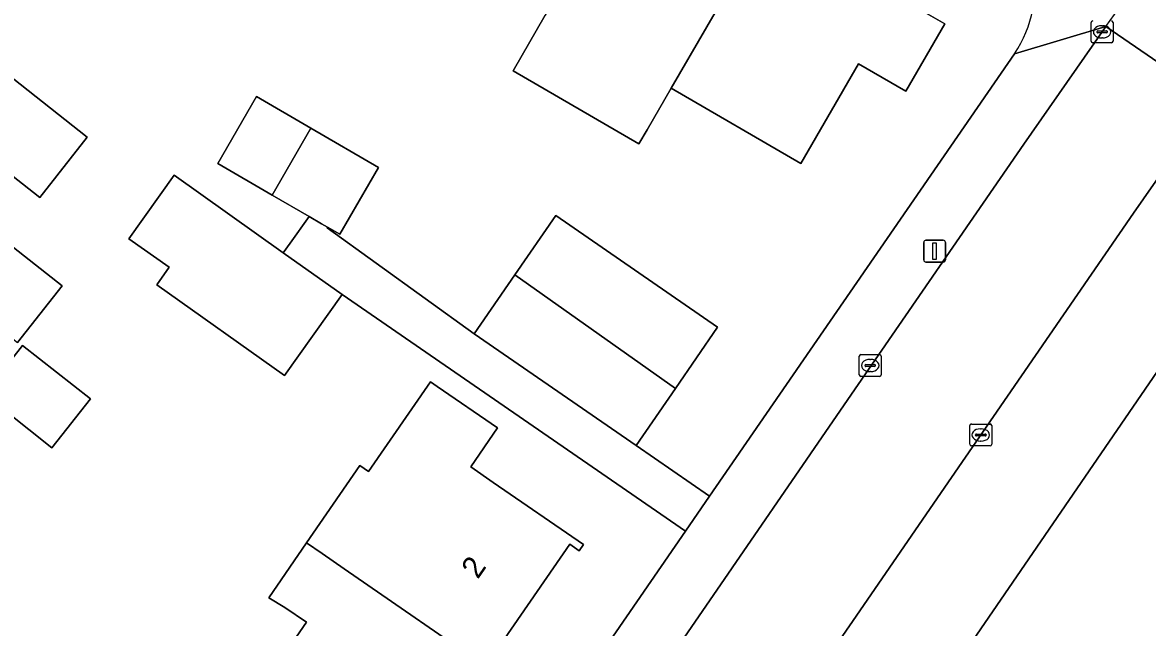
# Model space of a CAD drawing. Extents: x 160157 to 160921, y 381516 to 382045.
# Drawn here: x 160661.8 to 160713.1, y 381808.9 to 381836.5 of the extents above; entities that cross this region are included whole.
import ezdxf

# ---------------------------------------------------------------- set-up
doc = ezdxf.new("R2010")
doc.units = 0
for name, color, linetype in [('IMGEO_Erf', 7, 'Continuous'), ('IMGEO_Kolk', 7, 'Continuous'), ('IMGEO_Lichtmast', 7, 'Continuous'), ('IMGEO_Pand', 7, 'Continuous'), ('IMGEO_Pand_nummerreeks', 7, 'Continuous'), ('IMGEO_Rijbaan_lokaal_open', 7, 'Continuous'), ('IMGEO_Voetpad_onverhard', 7, 'Continuous'), ('IMGEO_Voetpad_open', 7, 'Continuous')]:
    doc.layers.add(name, color=color, linetype=linetype)

msp = doc.modelspace()

# ---------------------------------------------------------------- linework, layer by layer
at = {"layer": 'IMGEO_Erf'}
for points in [[(160701.768, 381837.681), (160703.91, 381836.439), (160702.128, 381833.366), (160699.968, 381834.618), (160697.333, 381830.075), (160691.421, 381833.503), (160690.32, 381831.604), (160689.953, 381830.972), (160684.21, 381834.303), (160685.678, 381836.834)], [(160668.746, 381829.534), (160673.729, 381826), (160674.043, 381826.443), (160674.917, 381827.652), (160673.223, 381828.634), (160670.738, 381830.074), (160672.505, 381833.121), (160674.99, 381831.679), (160678.068, 381829.896), (160676.302, 381826.849), (160675.752, 381827.168), (160675.732, 381827.144), (160682.435, 381822.299), (160684.296, 381824.999), (160686.154, 381827.695), (160693.541, 381822.604), (160691.617, 381819.813), (160689.822, 381817.208), (160693.176, 381814.897), (160707.078, 381835.076)], [(160651.567, 381806.643), (160675.928, 381789.86), (160692.079, 381813.304), (160676.409, 381824.1), (160673.783, 381820.397), (160667.957, 381824.529), (160668.528, 381825.335), (160666.692, 381826.637), (160668.746, 381829.534)], [(160719.08, 381828.577), (160705.185, 381808.313)], [(160661.424, 381826.236), (160663.639, 381824.494), (160661.607, 381821.911)], [(160672.564, 381805.927), (160674.782, 381809.143), (160673.803, 381809.818), (160673.072, 381810.264), (160674.793, 381812.761), (160677.226, 381816.289), (160677.621, 381816.017), (160680.448, 381820.118), (160680.755, 381819.906), (160683.504, 381818.011), (160682.279, 381816.233), (160683.308, 381815.523), (160687.425, 381812.686), (160687.229, 381812.402), (160686.795, 381812.701), (160683.076, 381807.306)]]:
    msp.add_lwpolyline(points, dxfattribs=at)
for points in [[(160658.239, 381831.971), (160660.4, 381834.718), (160664.786, 381831.267), (160662.625, 381828.52)], [(160661.833, 381821.771), (160664.929, 381819.334), (160663.176, 381817.106), (160660.08, 381819.542)]]:
    msp.add_lwpolyline(points, close=True, dxfattribs=at)
msp.add_arc((160702.334, 381838.235), 5.699, 326.3418, 52.9251, dxfattribs=at)
at = {"layer": 'IMGEO_Kolk'}
for p, q in [((160710.578, 381835.651), (160710.578, 381836.503)), ((160711.066, 381836.357), (160711.091, 381836.357)), ((160711.579, 381836.503), (160711.579, 381835.651)), ((160710.837, 381836.071), (160710.837, 381836.083)), ((160711.275, 381836.034), (160710.877, 381836.034)), ((160710.88, 381836.12), (160711.278, 381836.12)), ((160711.089, 381835.797), (160711.064, 381835.797)), ((160711.321, 381836.083), (160711.321, 381836.071)), ((160711.505, 381835.577), (160710.653, 381835.577)), ((160700.002, 381820.431), (160700.002, 381821.283)), ((160700.077, 381821.357), (160700.929, 381821.357)), ((160700.49, 381821.137), (160700.515, 381821.137)), ((160701.003, 381821.283), (160701.003, 381820.431)), ((160700.261, 381820.851), (160700.261, 381820.863)), ((160700.699, 381820.814), (160700.301, 381820.814)), ((160700.304, 381820.9), (160700.702, 381820.9)), ((160700.513, 381820.577), (160700.488, 381820.577)), ((160700.745, 381820.863), (160700.745, 381820.851)), ((160700.929, 381820.357), (160700.077, 381820.357)), ((160705.043, 381817.262), (160705.043, 381818.114)), ((160705.118, 381818.188), (160705.97, 381818.188)), ((160705.531, 381817.968), (160705.556, 381817.968)), ((160706.044, 381818.114), (160706.044, 381817.262)), ((160705.302, 381817.682), (160705.302, 381817.694)), ((160705.74, 381817.645), (160705.342, 381817.645)), ((160705.345, 381817.731), (160705.743, 381817.731)), ((160705.554, 381817.408), (160705.529, 381817.408)), ((160705.786, 381817.694), (160705.786, 381817.682)), ((160705.97, 381817.188), (160705.118, 381817.188))]:
    msp.add_line(p, q, dxfattribs=at)
for points in [[(160710.578, 381835.651), (160710.578, 381836.503)], [(160711.579, 381836.503), (160711.579, 381835.651)], [(160711.505, 381835.577), (160710.653, 381835.577)], [(160700.002, 381820.431), (160700.002, 381821.283)], [(160700.077, 381821.357), (160700.929, 381821.357)], [(160701.003, 381821.283), (160701.003, 381820.431)], [(160700.929, 381820.357), (160700.077, 381820.357)], [(160705.043, 381817.262), (160705.043, 381818.114)], [(160705.118, 381818.188), (160705.97, 381818.188)], [(160706.044, 381818.114), (160706.044, 381817.262)], [(160705.97, 381817.188), (160705.118, 381817.188)]]:
    msp.add_lwpolyline(points, dxfattribs=at)
for centre, radius, start, end in [((160710.655, 381836.501), 0.0765, 91.552, 178.448), ((160710.655, 381836.501), 0.0765, 91.552, 178.448), ((160711.503, 381836.501), 0.0765, 1.552, 88.448), ((160711.503, 381836.501), 0.0765, 1.552, 88.448), ((160710.877, 381836.08), 0.0403, 85.8775, 175.7526), ((160710.874, 381836.07), 0.0366, 178.938, 274.7102), ((160711.278, 381836.077), 0.043, 264.8664, 352.4533), ((160711.282, 381836.082), 0.0386, 1.7309, 96.639), ((160710.655, 381835.653), 0.0765, 181.552, 268.448), ((160710.655, 381835.653), 0.0765, 181.552, 268.448), ((160711.503, 381835.653), 0.0765, 271.552, 358.448), ((160711.503, 381835.653), 0.0765, 271.552, 358.448), ((160700.079, 381821.281), 0.0765, 91.552, 178.448), ((160700.079, 381821.281), 0.0765, 91.552, 178.448), ((160700.927, 381821.281), 0.0765, 1.552, 88.448), ((160700.927, 381821.281), 0.0765, 1.552, 88.448), ((160700.079, 381820.433), 0.0765, 181.552, 268.448), ((160700.079, 381820.433), 0.0765, 181.552, 268.448), ((160700.301, 381820.86), 0.0403, 85.8775, 175.7526), ((160700.298, 381820.85), 0.0366, 178.938, 274.7102), ((160700.702, 381820.857), 0.043, 264.8664, 352.4533), ((160700.706, 381820.862), 0.0386, 1.7309, 96.639), ((160700.927, 381820.433), 0.0765, 271.552, 358.448), ((160700.927, 381820.433), 0.0765, 271.552, 358.448), ((160705.12, 381818.112), 0.0765, 91.552, 178.448), ((160705.12, 381818.112), 0.0765, 91.552, 178.448), ((160705.968, 381818.112), 0.0765, 1.552, 88.448), ((160705.968, 381818.112), 0.0765, 1.552, 88.448), ((160705.342, 381817.691), 0.0403, 85.8775, 175.7526), ((160705.339, 381817.681), 0.0366, 178.938, 274.7102), ((160705.743, 381817.688), 0.043, 264.8664, 352.4533), ((160705.747, 381817.693), 0.0386, 1.7309, 96.639), ((160705.12, 381817.264), 0.0765, 181.552, 268.448), ((160705.12, 381817.264), 0.0765, 181.552, 268.448), ((160705.968, 381817.264), 0.0765, 271.552, 358.448), ((160705.968, 381817.264), 0.0765, 271.552, 358.448)]:
    msp.add_arc(centre, radius, start, end, dxfattribs=at)
for centre, major_axis, ratio, start_param, end_param in [((160711.065, 381836.077), (-0.387, 0.002), 0.722429, 4.712389, 7.853982), ((160711.09, 381836.077), (-0.39, 0.002), 0.717154, 1.570796, 4.712389), ((160700.489, 381820.857), (-0.387, 0.002), 0.722429, 4.712389, 7.853982), ((160700.514, 381820.857), (-0.39, 0.002), 0.717154, 1.570796, 4.712389), ((160705.53, 381817.688), (-0.387, 0.002), 0.722429, 4.712389, 7.853982), ((160705.555, 381817.688), (-0.39, 0.002), 0.717154, 1.570796, 4.712389)]:
    msp.add_ellipse(centre, major_axis=major_axis, ratio=ratio, start_param=start_param, end_param=end_param, dxfattribs=at)
at = {"layer": 'IMGEO_Lichtmast'}
for p, q in [((160703.044, 381826.572), (160703.834, 381826.572)), ((160703.834, 381826.572), (160703.044, 381826.572)), ((160702.944, 381825.672), (160702.944, 381826.472)), ((160702.944, 381826.472), (160702.944, 381825.672)), ((160703.934, 381826.472), (160703.934, 381825.672)), ((160703.934, 381825.672), (160703.934, 381826.472)), ((160703.834, 381825.572), (160703.044, 381825.572)), ((160703.044, 381825.572), (160703.834, 381825.572))]:
    msp.add_line(p, q, dxfattribs=at)
msp.add_lwpolyline([(160703.364, 381826.447), (160703.514, 381826.447), (160703.514, 381825.697), (160703.364, 381825.697), (160703.364, 381826.447)], dxfattribs=at)
for centre, start, end in [((160703.044, 381826.472), 90, 180), ((160703.044, 381826.472), 90, 180), ((160703.834, 381826.472), 0, 90), ((160703.834, 381826.472), 360, 90), ((160703.044, 381825.672), 180, 270), ((160703.044, 381825.672), 180, 270), ((160703.834, 381825.672), 270, 0), ((160703.834, 381825.672), 270, 0)]:
    msp.add_arc(centre, 0.1, start, end, dxfattribs=at)
at = {"layer": 'IMGEO_Pand'}
for points in [[(160696.301, 381841.911), (160696.119, 381842.016), (160695.896, 381841.632), (160690.52, 381844.749), (160690.758, 381845.159), (160690.571, 381845.267), (160685.678, 381836.834), (160684.21, 381834.303), (160689.953, 381830.972), (160690.32, 381831.604), (160691.421, 381833.503)], [(160691.421, 381833.503), (160697.333, 381830.075), (160699.968, 381834.618), (160702.128, 381833.366), (160703.91, 381836.439), (160701.768, 381837.681), (160702.24, 381838.495), (160701.879, 381838.705), (160701.682, 381838.365), (160696.295, 381841.489), (160696.48, 381841.807), (160696.301, 381841.911)], [(160664.786, 381831.267), (160660.4, 381834.718), (160658.239, 381831.971), (160662.625, 381828.52)], [(160674.99, 381831.679), (160672.505, 381833.121), (160670.738, 381830.074), (160673.223, 381828.634)], [(160674.99, 381831.679), (160673.223, 381828.634), (160674.917, 381827.652), (160675.48, 381827.325), (160675.752, 381827.168), (160676.302, 381826.849), (160678.068, 381829.896)], [(160673.729, 381826), (160668.746, 381829.534), (160666.692, 381826.637), (160668.528, 381825.335), (160667.957, 381824.529), (160673.783, 381820.397), (160676.409, 381824.1)], [(160684.296, 381824.999), (160691.617, 381819.813), (160693.541, 381822.604), (160686.154, 381827.695)], [(160663.639, 381824.494), (160661.424, 381826.236), (160659.392, 381823.653), (160661.607, 381821.911)], [(160684.296, 381824.999), (160682.435, 381822.299), (160689.822, 381817.208), (160691.617, 381819.813)], [(160660.08, 381819.542), (160663.176, 381817.106), (160664.929, 381819.334), (160661.833, 381821.771)], [(160683.308, 381815.523), (160682.279, 381816.233), (160683.504, 381818.011), (160680.755, 381819.906), (160680.448, 381820.118), (160677.621, 381816.017), (160677.226, 381816.289), (160674.793, 381812.761), (160675.497, 381812.275), (160676.513, 381811.574), (160683.43, 381806.8), (160683.552, 381806.978), (160683.076, 381807.306), (160686.795, 381812.701), (160687.229, 381812.402), (160687.425, 381812.686)], [(160676.513, 381811.574), (160675.497, 381812.275), (160674.793, 381812.761), (160673.072, 381810.264), (160673.803, 381809.818), (160674.782, 381809.143), (160672.564, 381805.927), (160679.442, 381801.183), (160679.537, 381801.322), (160679.14, 381801.595), (160682.831, 381806.949), (160683.307, 381806.621), (160683.43, 381806.8)]]:
    msp.add_lwpolyline(points, close=True, dxfattribs=at)
at = {"layer": 'IMGEO_Rijbaan_lokaal_open'}
for points in [[(160658.96, 381750), (160667.503, 381762.414), (160670.296, 381766.471), (160700.524, 381810.394), (160703.573, 381814.824), (160712.504, 381827.801), (160716.028, 381832.837), (160716.089, 381833.009), (160711.248, 381836.325), (160711.08, 381836.076), (160707.501, 381830.956), (160699.651, 381819.545), (160692.328, 381808.901), (160680.332, 381791.464), (160678.334, 381788.56), (160651.806, 381750)], [(160711.248, 381836.325), (160716.089, 381833.009)]]:
    msp.add_lwpolyline(points, dxfattribs=at)
msp.add_arc((160706.596, 381840.091), 5.985, 321.0131, 61.9743, dxfattribs=at)
at = {"layer": 'IMGEO_Voetpad_onverhard'}
msp.add_lwpolyline([(160682.435, 381822.299), (160675.732, 381827.144), (160675.752, 381827.168), (160675.48, 381827.325), (160674.917, 381827.652), (160674.043, 381826.443), (160673.729, 381826), (160676.409, 381824.1), (160692.079, 381813.304), (160693.176, 381814.897), (160689.822, 381817.208)], close=True, dxfattribs=at)
at = {"layer": 'IMGEO_Voetpad_open'}
msp.add_lwpolyline([(160707.501, 381830.956), (160711.08, 381836.076), (160711.248, 381836.325), (160707.078, 381835.076), (160693.176, 381814.897), (160692.079, 381813.304), (160675.928, 381789.86), (160675.328, 381788.989), (160648.467, 381750), (160641.671, 381740.128), (160640.592, 381738.561), (160605.905, 381688.17), (160606.806, 381684.4), (160609.452, 381688.229), (160610.996, 381690.462), (160614.441, 381695.549), (160641.13, 381734.448), (160643.136, 381737.367), (160651.806, 381750), (160678.334, 381788.56), (160680.332, 381791.464), (160692.328, 381808.901), (160699.651, 381819.545)], close=True, dxfattribs=at)
for points in [[(160707.078, 381835.076), (160711.248, 381836.325)], [(160716.089, 381833.009), (160716.028, 381832.837), (160712.504, 381827.801), (160703.573, 381814.824), (160700.524, 381810.394), (160670.296, 381766.471), (160667.503, 381762.414), (160658.96, 381750), (160642.496, 381725.9), (160640.187, 381722.521), (160619.05, 381691.582), (160615.999, 381687.121), (160614.454, 381684.835), (160611.203, 381680.025), (160615.694, 381677.246), (160615.835, 381678.381), (160616.408, 381679.37), (160644.455, 381719.97), (160645.316, 381721.217), (160665.2, 381750)], [(160665.2, 381750), (160672.541, 381760.705), (160673.051, 381761.449), (160674.255, 381763.205), (160674.789, 381763.984), (160704.201, 381806.878), (160705.185, 381808.313), (160719.08, 381828.577)]]:
    msp.add_lwpolyline(points, dxfattribs=at)
for centre, radius, start, end in [((160706.596, 381840.091), 5.985, 321.0131, 61.9743), ((160702.334, 381838.235), 5.699, 326.3418, 52.9251)]:
    msp.add_arc(centre, radius, start, end, dxfattribs=at)

# ---------------------------------------------------------------- texts
at = {"layer": 'IMGEO_Pand_nummerreeks'}
msp.add_text('2', height=1, rotation=55.256, dxfattribs=at).set_placement((160682.602, 381811.078))

doc.saveas('drawing.dxf')
